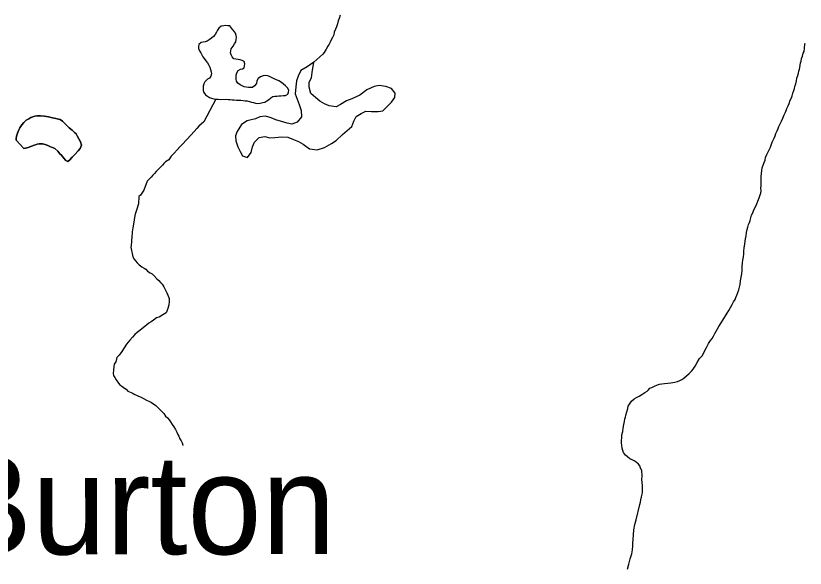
# Model space of a CAD drawing. Extents: x 0 to 34, y 0 to 22.
# Drawn here: x 4.731 to 5.632, y 20.03 to 20.661 of the extents above; entities that cross this region are included whole.
import ezdxf

# ---------------------------------------------------------------- set-up
doc = ezdxf.new("R2010")
doc.units = 0
for name, color, linetype in [('GM_X_Minor_Lake', 7, 'Continuous'), ('GM_X_Minor_Lake_Text', 7, 'Continuous'), ('GM_X_Minor_River', 7, 'Continuous')]:
    doc.layers.add(name, color=color, linetype=linetype)

msp = doc.modelspace()

# ---------------------------------------------------------------- linework, layer by layer
at = {"layer": 'GM_X_Minor_Lake'}
for points in [[(4.97873, 20.64532), (4.97528, 20.65004), (4.973, 20.65), (4.97072, 20.65035), (4.96845, 20.64994), (4.96542, 20.64953), (4.96279, 20.64721), (4.9613, 20.64492), (4.96019, 20.64262), (4.9587, 20.63995), (4.95646, 20.63764), (4.9542, 20.63571), (4.95157, 20.63378), (4.94931, 20.63261), (4.94704, 20.63182), (4.94477, 20.63141), (4.9425, 20.631), (4.93987, 20.62869), (4.93952, 20.62641), (4.93955, 20.62413), (4.94072, 20.62149), (4.94226, 20.61923), (4.94459, 20.61471), (4.94614, 20.61245), (4.94807, 20.60982), (4.94962, 20.60756), (4.95117, 20.60492), (4.95233, 20.60266), (4.95312, 20.60001), (4.95392, 20.59737), (4.95432, 20.59509), (4.9536, 20.59243), (4.95211, 20.59013), (4.94985, 20.58896), (4.94685, 20.58589), (4.94574, 20.58359), (4.94501, 20.58092), (4.94466, 20.57826)], [(5.04151, 20.57195), (5.04224, 20.57424), (5.04259, 20.57652), (5.04104, 20.57916), (5.03874, 20.58141), (5.03414, 20.58514), (5.03108, 20.587), (5.02841, 20.5881), (5.02574, 20.58959), (5.02344, 20.59069), (5.02116, 20.5918), (5.01848, 20.59291), (5.0162, 20.59326), (5.01317, 20.59284), (5.01015, 20.59166), (5.00752, 20.58972), (5.00603, 20.58705), (5.00569, 20.58401), (5.00345, 20.58132), (5.00119, 20.57939), (4.99664, 20.57933), (4.99398, 20.58006), (4.99169, 20.5804), (4.9894, 20.58151), (4.98711, 20.58262), (4.98444, 20.58448), (4.98289, 20.58674), (4.98248, 20.58901), (4.98242, 20.59357), (4.98315, 20.59623), (4.98464, 20.59891), (4.98727, 20.60046), (4.98955, 20.60088), (4.99181, 20.60204), (4.99251, 20.60661), (4.99172, 20.60925), (4.98943, 20.61036), (4.98714, 20.61109), (4.98486, 20.61144), (4.9822, 20.61179), (4.97992, 20.61214), (4.97799, 20.61439), (4.97683, 20.61665), (4.97604, 20.61892), (4.97639, 20.62158), (4.97674, 20.62386), (4.97898, 20.62655), (4.98047, 20.62923), (4.98196, 20.63152), (4.98268, 20.63419), (4.98303, 20.63647), (4.98263, 20.63874), (4.98184, 20.64139), (4.97952, 20.64478), (4.97873, 20.64532)], [(5.07109, 20.60837), (5.06351, 20.60305), (5.0563, 20.59886), (5.05326, 20.5924), (5.05136, 20.58708), (5.0506, 20.58024), (5.04984, 20.57227), (5.05439, 20.56012), (5.05667, 20.55328), (5.05705, 20.54607), (5.05211, 20.53999), (5.04604, 20.5377), (5.04073, 20.53883), (5.03428, 20.54073), (5.02783, 20.54262), (5.02252, 20.54489), (5.01607, 20.54678), (5.00962, 20.54601), (5.00469, 20.54373), (4.9952, 20.54144), (4.98875, 20.53725), (4.98382, 20.52927), (4.98192, 20.52433), (4.9823, 20.51864), (4.98457, 20.5118), (4.98723, 20.50649), (4.98988, 20.50155), (4.99558, 20.49966), (4.99975, 20.50536), (5.00127, 20.51182), (5.00355, 20.51714), (5.00886, 20.52247), (5.01531, 20.52361), (5.021, 20.5221), (5.02669, 20.52249), (5.03428, 20.52325), (5.04149, 20.52288), (5.04794, 20.52023), (5.05363, 20.51796)], [(5.07109, 20.60837), (5.06351, 20.60305), (5.0563, 20.59886), (5.05326, 20.5924), (5.05136, 20.58708), (5.0506, 20.58024), (5.04984, 20.57227), (5.05439, 20.56012), (5.05667, 20.55328), (5.05705, 20.54607), (5.05211, 20.53999), (5.04604, 20.5377), (5.04073, 20.53883), (5.03428, 20.54073), (5.02783, 20.54262), (5.02252, 20.54489), (5.01607, 20.54678), (5.00962, 20.54601), (5.00469, 20.54373), (4.9952, 20.54144), (4.98875, 20.53725), (4.98382, 20.52927), (4.98192, 20.52433), (4.9823, 20.51864), (4.98457, 20.5118), (4.98723, 20.50649), (4.98988, 20.50155), (4.99558, 20.49966), (4.99975, 20.50536), (5.00127, 20.51182), (5.00355, 20.51714), (5.00886, 20.52247), (5.01531, 20.52361), (5.021, 20.5221), (5.02669, 20.52249), (5.03428, 20.52325), (5.04149, 20.52288), (5.04794, 20.52023), (5.05363, 20.51796), (5.05894, 20.51492), (5.06615, 20.50962), (5.07487, 20.50849), (5.08322, 20.51116), (5.09119, 20.51572), (5.0965, 20.51915), (5.10371, 20.52599), (5.11434, 20.53512), (5.11662, 20.5412), (5.11927, 20.54652), (5.12496, 20.54995), (5.13066, 20.55261), (5.13711, 20.55224), (5.14469, 20.55224), (5.15001, 20.55301), (5.15987, 20.5629), (5.16367, 20.56822), (5.16405, 20.57316), (5.15987, 20.57847), (5.15342, 20.58074), (5.14584, 20.58187), (5.14014, 20.58073), (5.1318, 20.57692), (5.12345, 20.57083), (5.11434, 20.56664), (5.10827, 20.56436), (5.10144, 20.56017), (5.09651, 20.55751), (5.08854, 20.55864), (5.08323, 20.56091), (5.07792, 20.56394), (5.07298, 20.56812), (5.06767, 20.57267), (5.06578, 20.57988), (5.06578, 20.58558), (5.06844, 20.59052), (5.06919, 20.5966), (5.07109, 20.60837)], [(5.05363, 20.51796), (5.05894, 20.51492), (5.06615, 20.50962), (5.07487, 20.50849), (5.08322, 20.51116), (5.09119, 20.51572), (5.0965, 20.51915), (5.10371, 20.52599), (5.11434, 20.53512), (5.11662, 20.5412), (5.11927, 20.54652), (5.12496, 20.54995), (5.13066, 20.55261), (5.13711, 20.55224), (5.14469, 20.55224), (5.15001, 20.55301), (5.15987, 20.5629), (5.16367, 20.56822), (5.16405, 20.57316), (5.15987, 20.57847), (5.15342, 20.58074), (5.14584, 20.58187), (5.14014, 20.58073), (5.1318, 20.57692), (5.12345, 20.57083), (5.11434, 20.56664), (5.10827, 20.56436), (5.10144, 20.56017), (5.09651, 20.55751), (5.08854, 20.55864), (5.08323, 20.56091), (5.07792, 20.56394), (5.07298, 20.56812), (5.06767, 20.57267), (5.06578, 20.57988), (5.06578, 20.58558), (5.06844, 20.59052), (5.06919, 20.5966), (5.07109, 20.60837)], [(4.94466, 20.57826), (4.94469, 20.57599), (4.94548, 20.57372), (4.94741, 20.57109), (4.952, 20.56811), (4.95429, 20.56738), (4.95695, 20.56666), (4.95923, 20.56631), (4.96189, 20.56634), (4.96417, 20.56599), (4.971, 20.56608), (4.97328, 20.56573), (4.97556, 20.56577), (4.97784, 20.56542), (4.98012, 20.56545), (4.98278, 20.5651), (4.98771, 20.56517), (4.99037, 20.56482), (4.99265, 20.56447), (4.99493, 20.56412), (4.9976, 20.5634), (4.99988, 20.56267), (5.00216, 20.56232), (5.00445, 20.56159), (5.00711, 20.56125), (5.00976, 20.56166), (5.01279, 20.56246), (5.01506, 20.56287), (5.01732, 20.56442), (5.01958, 20.56559), (5.02221, 20.56752), (5.02447, 20.56907), (5.02674, 20.56948), (5.02902, 20.56951), (5.03129, 20.56992), (5.03357, 20.56995), (5.0366, 20.57037), (5.03887, 20.5704), (5.04151, 20.57195)], [(4.80106, 20.52431), (4.79987, 20.52657), (4.79793, 20.52804), (4.79521, 20.53064), (4.79211, 20.53362), (4.789, 20.53659), (4.78628, 20.53919), (4.78434, 20.54105), (4.78164, 20.54289), (4.77973, 20.54323), (4.77667, 20.54392), (4.77285, 20.54498), (4.76826, 20.54602), (4.76368, 20.54668), (4.7591, 20.54734), (4.7553, 20.54725), (4.75264, 20.54682), (4.75038, 20.54601), (4.74811, 20.5452), (4.74587, 20.54363), (4.74286, 20.54204), (4.74024, 20.53971), (4.73802, 20.537), (4.73581, 20.53353), (4.73434, 20.53122), (4.7329, 20.52739), (4.73183, 20.52395), (4.73152, 20.5209), (4.73134, 20.51943)], [(4.73134, 20.51943), (4.73152, 20.5209), (4.73183, 20.52395), (4.7329, 20.52739), (4.73434, 20.53122), (4.73581, 20.53353), (4.73802, 20.537), (4.74024, 20.53971), (4.74286, 20.54204), (4.74587, 20.54363), (4.74811, 20.5452), (4.75038, 20.54601), (4.75264, 20.54682), (4.7553, 20.54725), (4.7591, 20.54734), (4.76368, 20.54668), (4.76826, 20.54602), (4.77285, 20.54498), (4.77667, 20.54392), (4.77973, 20.54323), (4.78164, 20.54289), (4.78434, 20.54105), (4.78628, 20.53919), (4.789, 20.53659), (4.79211, 20.53362), (4.79521, 20.53064), (4.79793, 20.52804), (4.79987, 20.52657), (4.80106, 20.52431), (4.80501, 20.51756), (4.80585, 20.51378), (4.80441, 20.50994), (4.80218, 20.50724), (4.79847, 20.50298), (4.79549, 20.49987), (4.79252, 20.49677), (4.79027, 20.49482), (4.78796, 20.49629), (4.78562, 20.49928), (4.78327, 20.50226), (4.78134, 20.50374), (4.77899, 20.50673), (4.7755, 20.5097), (4.77358, 20.51079), (4.77166, 20.51151), (4.76974, 20.51223), (4.76744, 20.51332), (4.76437, 20.51439), (4.76131, 20.51509), (4.75751, 20.515), (4.75523, 20.51496), (4.75334, 20.51415), (4.7507, 20.51334), (4.74806, 20.51214), (4.74504, 20.51093), (4.74202, 20.51011), (4.74012, 20.50969), (4.73134, 20.51943)], [(4.73134, 20.51943), (4.74012, 20.50969), (4.74202, 20.51011), (4.74504, 20.51093), (4.74806, 20.51214), (4.7507, 20.51334), (4.75334, 20.51415), (4.75523, 20.51496), (4.75751, 20.515), (4.76131, 20.51509), (4.76437, 20.51439), (4.76744, 20.51332), (4.76974, 20.51223), (4.77166, 20.51151), (4.77358, 20.51079), (4.7755, 20.5097), (4.77899, 20.50673), (4.78134, 20.50374), (4.78327, 20.50226), (4.78562, 20.49928), (4.78796, 20.49629), (4.79027, 20.49482), (4.79252, 20.49677), (4.79549, 20.49987), (4.79847, 20.50298), (4.80218, 20.50724), (4.80441, 20.50994), (4.80585, 20.51378), (4.80501, 20.51756), (4.80106, 20.52431)]]:
    msp.add_lwpolyline(points, dxfattribs=at)
at = {"layer": 'GM_X_Minor_River'}
for points in [[(5.10128, 20.66231), (5.10023, 20.65849), (5.09876, 20.65579), (5.09807, 20.65236), (5.097, 20.64892), (5.09592, 20.64623), (5.09447, 20.64278), (5.09378, 20.63973), (5.09232, 20.63665), (5.09086, 20.63396), (5.08977, 20.63128), (5.08868, 20.62898), (5.08721, 20.62667), (5.08538, 20.62321), (5.0828, 20.61935), (5.08132, 20.61742), (5.07109, 20.60837)], [(5.59763, 20.52415), (5.59833, 20.52682), (5.59979, 20.52989), (5.60087, 20.53258), (5.60196, 20.53488), (5.60342, 20.53795), (5.60487, 20.54102), (5.60632, 20.54447), (5.60776, 20.54831), (5.60958, 20.55214), (5.61103, 20.5556), (5.61248, 20.55867), (5.61357, 20.56135), (5.61462, 20.56517), (5.61609, 20.56786), (5.6168, 20.57016), (5.61788, 20.57322), (5.61896, 20.57591), (5.61967, 20.5782), (5.62001, 20.58049), (5.62108, 20.58355), (5.62177, 20.58699), (5.62246, 20.59004), (5.62354, 20.5931), (5.62424, 20.59578), (5.62457, 20.59807), (5.62529, 20.60036), (5.62562, 20.60227), (5.62595, 20.60493), (5.62665, 20.60761), (5.62737, 20.60952), (5.62769, 20.61257), (5.62877, 20.61525), (5.62946, 20.61869), (5.63056, 20.62061), (5.63124, 20.62443), (5.63152, 20.62899), (5.63187, 20.63014)], [(4.95923, 20.56631), (4.94565, 20.54037), (4.94005, 20.53531), (4.93744, 20.5326), (4.93448, 20.52911), (4.93075, 20.52523), (4.92109, 20.51476), (4.91811, 20.51166), (4.91514, 20.50817), (4.9118, 20.50468), (4.90844, 20.50119), (4.90549, 20.49695), (4.90174, 20.49458), (4.89988, 20.49264), (4.8984, 20.49071), (4.89654, 20.48877), (4.89318, 20.48566), (4.89132, 20.48372), (4.88947, 20.4814), (4.88723, 20.47945), (4.88537, 20.47713), (4.88352, 20.47519), (4.88091, 20.47247), (4.87695, 20.46213), (4.87327, 20.45635), (4.87139, 20.45517), (4.87119, 20.4468), (4.86868, 20.43953), (4.86726, 20.43494), (4.86658, 20.43112), (4.86555, 20.42578), (4.86455, 20.4193), (4.86422, 20.41701), (4.86389, 20.41473), (4.86393, 20.41245), (4.8636, 20.41016), (4.86298, 20.40369), (4.8627, 20.39912), (4.86236, 20.39721), (4.86408, 20.38813), (4.86449, 20.38624), (4.86607, 20.38362), (4.86764, 20.38137), (4.86959, 20.37913), (4.87192, 20.3769), (4.87501, 20.37469), (4.87733, 20.37322), (4.87925, 20.37212), (4.8812, 20.36989), (4.88429, 20.36767), (4.8866, 20.36658), (4.88893, 20.36435), (4.89204, 20.361), (4.89437, 20.35915), (4.89632, 20.35692), (4.89788, 20.35505), (4.89985, 20.35167), (4.90144, 20.34867), (4.90342, 20.34491), (4.90462, 20.34228), (4.90542, 20.34039), (4.90622, 20.33851), (4.90591, 20.33509), (4.90561, 20.33128), (4.90456, 20.32708), (4.90349, 20.32401), (4.90277, 20.3221), (4.89863, 20.31973), (4.8945, 20.31736), (4.89148, 20.31653), (4.88811, 20.3138), (4.88549, 20.31184), (4.88286, 20.31027), (4.88062, 20.30832), (4.87238, 20.30206), (4.86939, 20.29971), (4.86678, 20.29738), (4.86418, 20.29428), (4.86121, 20.2908), (4.8575, 20.28654), (4.85455, 20.28229), (4.85198, 20.27806), (4.84902, 20.27381), (4.84642, 20.2711), (4.845, 20.26613), (4.84316, 20.26343), (4.84284, 20.26076), (4.84254, 20.25657), (4.84224, 20.25277), (4.84267, 20.2505), (4.84387, 20.24824), (4.84544, 20.24562), (4.84818, 20.24188), (4.84975, 20.24001), (4.85206, 20.23854), (4.85516, 20.23595), (4.85709, 20.23485), (4.85903, 20.23261)], [(5.44231, 20.22707), (5.44532, 20.22903), (5.4487, 20.231), (5.45133, 20.23258), (5.45319, 20.23414), (5.45467, 20.23607), (5.45694, 20.23688), (5.45995, 20.23847), (5.46334, 20.24006), (5.46561, 20.24049), (5.46827, 20.24093), (5.4713, 20.24137), (5.47509, 20.24184), (5.47851, 20.24229), (5.48306, 20.24277), (5.48609, 20.2436), (5.48873, 20.24479), (5.49098, 20.24598), (5.49323, 20.24755), (5.49622, 20.25027), (5.49958, 20.25301), (5.50219, 20.25534), (5.50405, 20.25766), (5.50625, 20.26113), (5.50845, 20.26536), (5.51139, 20.26998), (5.51474, 20.27347), (5.51655, 20.27769), (5.51911, 20.28269), (5.52167, 20.2873), (5.52389, 20.29039), (5.52574, 20.29271), (5.5272, 20.2954), (5.52866, 20.29847), (5.53012, 20.30117), (5.53159, 20.30386), (5.53343, 20.30656), (5.536, 20.31079), (5.53784, 20.31387), (5.543, 20.32158), (5.54484, 20.32467), (5.54667, 20.32812), (5.54849, 20.33158), (5.54995, 20.33465), (5.55179, 20.33735), (5.55288, 20.33966), (5.55397, 20.34234), (5.55504, 20.3454), (5.55612, 20.34847), (5.55681, 20.35152), (5.55751, 20.35458), (5.55818, 20.35877), (5.55885, 20.36296), (5.55953, 20.36678), (5.55983, 20.37058), (5.56011, 20.37515), (5.56041, 20.37934), (5.56072, 20.38238), (5.5614, 20.3862), (5.56171, 20.38924), (5.56202, 20.39267), (5.56232, 20.39648), (5.56299, 20.40067), (5.5633, 20.4041), (5.56362, 20.40676), (5.56431, 20.4102), (5.56499, 20.41401), (5.56567, 20.41745), (5.56638, 20.42012), (5.56707, 20.42318), (5.56816, 20.42548), (5.56888, 20.42777), (5.56996, 20.43046), (5.57066, 20.43351), (5.57212, 20.43621), (5.57319, 20.43965), (5.57502, 20.44311), (5.57684, 20.44657), (5.57792, 20.44963), (5.57936, 20.45346), (5.58043, 20.4569), (5.58115, 20.45882), (5.58147, 20.46148), (5.5814, 20.46452), (5.58173, 20.46719), (5.58167, 20.46985), (5.58162, 20.47213), (5.58156, 20.47478), (5.5815, 20.47782), (5.58249, 20.48468), (5.58281, 20.48773), (5.58388, 20.49079), (5.58496, 20.49386), (5.58604, 20.49654), (5.58674, 20.4996), (5.58819, 20.50304), (5.59001, 20.50689), (5.59219, 20.51149), (5.59435, 20.51724), (5.59654, 20.52146), (5.59763, 20.52415)], [(4.85903, 20.23261), (4.86249, 20.23117), (4.8648, 20.23008), (4.86672, 20.22898), (4.86864, 20.22826), (4.87095, 20.22679), (4.87402, 20.22572), (4.87671, 20.22426), (4.88017, 20.22243), (4.88363, 20.22099), (4.88593, 20.2199), (4.89096, 20.21621), (4.89369, 20.21323), (4.89563, 20.21137), (4.89757, 20.20951), (4.8999, 20.20728), (4.90186, 20.20429), (4.90419, 20.20206), (4.90615, 20.19982), (4.90772, 20.19758), (4.9093, 20.19457), (4.91126, 20.19195), (4.91322, 20.18896), (4.91481, 20.18595), (4.91601, 20.18332), (4.91719, 20.18144), (4.9184, 20.17805), (4.91959, 20.1758), (4.92078, 20.17354), (4.9216, 20.1709), (4.92161, 20.17052)], [(5.42905, 20.02919), (5.43045, 20.03492), (5.43222, 20.04104), (5.434, 20.04678), (5.43466, 20.05135), (5.43533, 20.05593), (5.43526, 20.05897), (5.43555, 20.06315), (5.43582, 20.06848), (5.43646, 20.07419), (5.43747, 20.08029), (5.43887, 20.08564), (5.44306, 20.10321), (5.44377, 20.10589), (5.44447, 20.10857), (5.44516, 20.112), (5.44585, 20.11505), (5.44618, 20.11734), (5.44613, 20.12), (5.44602, 20.12493), (5.44549, 20.13176), (5.44579, 20.13557), (5.44575, 20.13785), (5.44532, 20.14012), (5.44527, 20.14202), (5.44408, 20.14465), (5.44326, 20.14729), (5.4417, 20.14916), (5.43898, 20.15176), (5.43667, 20.15323), (5.43436, 20.15432), (5.43167, 20.1554), (5.42897, 20.15762), (5.42664, 20.15947), (5.42468, 20.16247), (5.42387, 20.16473), (5.42304, 20.16775), (5.4226, 20.17078), (5.42215, 20.17381), (5.42209, 20.17685), (5.42242, 20.17914), (5.42272, 20.18294), (5.42378, 20.18676), (5.42408, 20.19057), (5.42475, 20.19477), (5.42581, 20.19821), (5.42614, 20.20088), (5.42686, 20.20279), (5.42719, 20.20508), (5.42931, 20.21272), (5.43001, 20.2154), (5.43148, 20.21771), (5.43369, 20.22118), (5.43668, 20.2239), (5.4393, 20.22548), (5.44231, 20.22707)]]:
    msp.add_lwpolyline(points, dxfattribs=at)

# ---------------------------------------------------------------- texts
at = {"layer": 'GM_X_Minor_Lake_Text'}
msp.add_text('Burton', height=0.113704, rotation=0.06697, dxfattribs=at).set_placement((4.64819, 20.04607))

doc.saveas('drawing.dxf')
